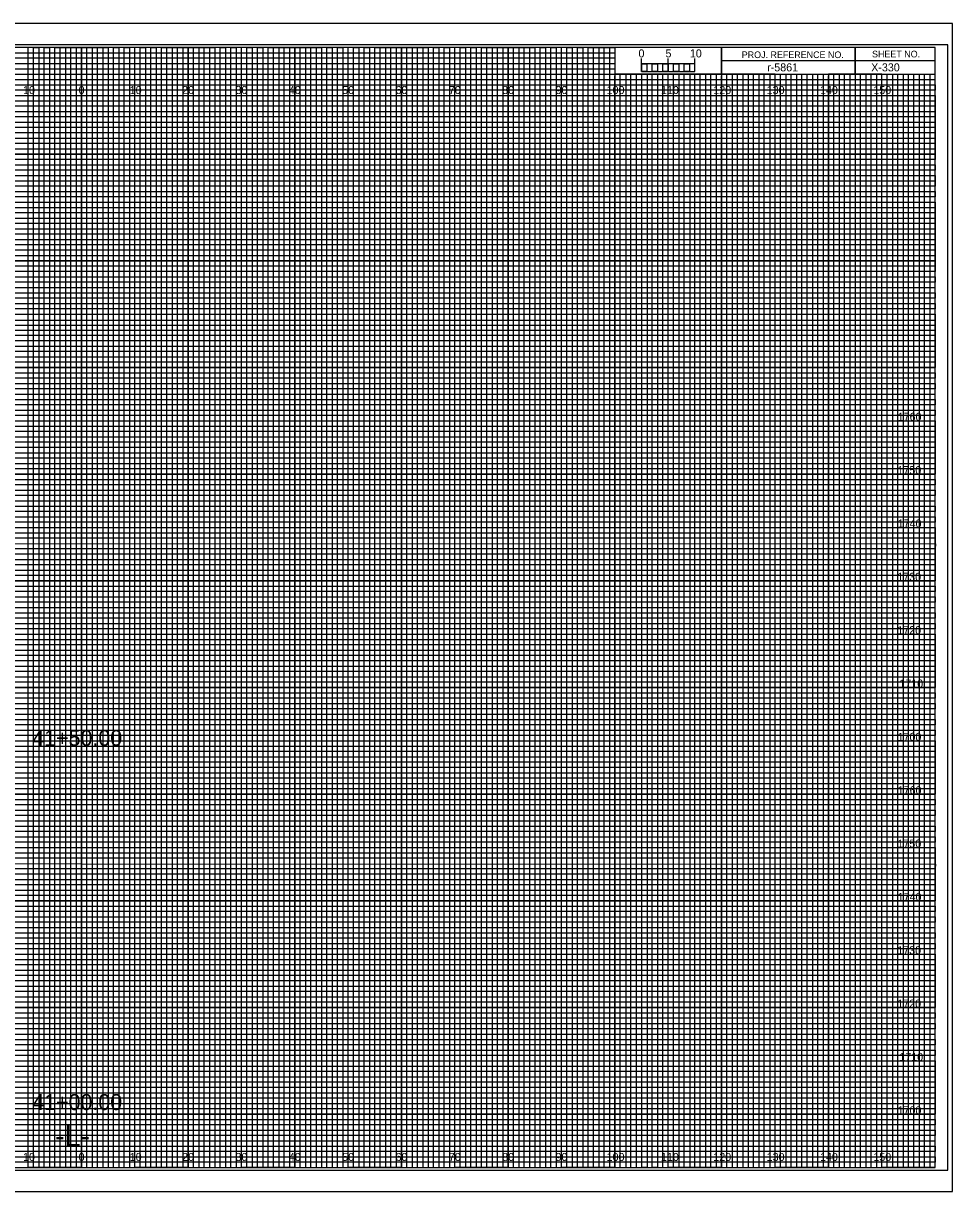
# Model space of a CAD drawing. Extents: x -15 to 323, y -5 to 6170.
# Drawn here: x 149.1 to 323.3, y 5715.5 to 5934.5 of the extents above; entities that cross this region are included whole.
import ezdxf

# ---------------------------------------------------------------- set-up
doc = ezdxf.new("R2010")
doc.units = 0
for name, color, linetype in [('Prop XS Alignment Label', 7, 'Continuous'), ('Prop XS Bar Scale Labels', 7, 'Continuous'), ('Prop XS DDE', 7, 'Continuous'), ('Prop XS DDE Earthwork Shape', 7, 'Continuous'), ('Prop XS DDE Slope Text', 7, 'Continuous'), ('Prop XS DDE Text', 7, 'Continuous'), ('Prop XS Earthwork Shape', 7, 'Continuous'), ('Prop XS Noise Wall', 7, 'Continuous'), ('Prop XS Project Number', 7, 'Continuous'), ('Prop XS Retaining Wall', 7, 'Continuous'), ('Prop XS Station Labels', 7, 'Continuous'), ('Prop XS Temporary Shoring', 7, 'Continuous'), ('Scratch_Level_3', 7, 'Continuous'), ('Scratch_Level_7', 7, 'Continuous'), ('Scratch_Level_8', 7, 'Continuous'), ('Sheet Cross Section Grid Minor 1 CELL', 7, 'Continuous')]:
    doc.layers.add(name, color=color, linetype=linetype)

msp = doc.modelspace()

# ---------------------------------------------------------------- linework, layer by layer
at = {"layer": 'Prop XS Alignment Label'}
for p, q in [((265, 5925.49), (265, 5927.9)), ((265, 5926.9), (265, 5927.9)), ((270, 5925.49), (270, 5927.9)), ((275, 5925.49), (275, 5927.9)), ((275, 5926.9), (275, 5927.9))]:
    msp.add_line(p, q, dxfattribs=at)
for points in [[(275, 5926.9), (265, 5926.9), (265, 5925.49), (275, 5925.49)], [(265, 5926.9), (266, 5926.9), (266, 5925.49), (265, 5925.49)], [(267, 5926.9), (268, 5926.9), (268, 5925.49), (267, 5925.49)], [(269, 5926.9), (270, 5926.9), (270, 5925.49), (269, 5925.49)], [(271, 5926.9), (272, 5926.9), (272, 5925.49), (271, 5925.49)], [(273, 5926.9), (274, 5926.9), (274, 5925.49), (273, 5925.49)]]:
    msp.add_lwpolyline(points, close=True, dxfattribs=at)
at = {"layer": 'Prop XS DDE'}
msp.add_lwpolyline([(-13.4, 5715.5), (323.3, 5715.5), (323.3, 5934.5), (-13.4, 5934.5)], close=True, dxfattribs=at)
at = {"layer": 'Prop XS DDE Slope Text'}
msp.add_lwpolyline([(-10.8, 5719.5), (322.4, 5719.5), (322.4, 5930.5), (-10.8, 5930.5)], close=True, dxfattribs=at)
at = {"layer": 'Prop XS DDE Text'}
for p, q in [((150, 5720), (150, 5930)), ((160, 5720), (160, 5930)), ((170, 5720), (170, 5930)), ((180, 5720), (180, 5930)), ((190, 5720), (190, 5930)), ((200, 5720), (200, 5930)), ((210, 5720), (210, 5930)), ((220, 5720), (220, 5930)), ((230, 5720), (230, 5930)), ((240, 5720), (240, 5930)), ((250, 5720), (250, 5930)), ((260, 5720), (260, 5924.69)), ((270, 5720), (270, 5924.69)), ((280, 5720), (280, 5924.69)), ((290, 5720), (290, 5924.69)), ((300, 5720), (300, 5924.69)), ((310, 5720), (310, 5924.69)), ((0, 5920), (320, 5920)), ((0, 5910), (320, 5910)), ((0, 5900), (320, 5900)), ((0, 5890), (320, 5890)), ((0, 5880), (320, 5880)), ((0, 5870), (320, 5870)), ((0, 5860), (320, 5860)), ((0, 5850), (320, 5850)), ((0, 5840), (320, 5840)), ((0, 5830), (320, 5830)), ((0, 5820), (320, 5820)), ((0, 5810), (320, 5810)), ((0, 5800), (320, 5800)), ((0, 5790), (320, 5790)), ((0, 5780), (320, 5780)), ((0, 5770), (320, 5770)), ((0, 5760), (320, 5760)), ((0, 5750), (320, 5750)), ((0, 5740), (320, 5740)), ((0, 5730), (320, 5730))]:
    msp.add_line(p, q, dxfattribs=at)
at = {"layer": 'Prop XS Earthwork Shape'}
for p, q in [((150, 5930), (140, 5930)), ((150, 5720), (150, 5930)), ((170, 5930), (160, 5930)), ((160, 5930), (160, 5720)), ((170, 5720), (170, 5930)), ((190, 5930), (180, 5930)), ((180, 5930), (180, 5720)), ((190, 5720), (190, 5930)), ((210, 5930), (200, 5930)), ((200, 5930), (200, 5720)), ((210, 5720), (210, 5930)), ((230, 5930), (220, 5930)), ((220, 5930), (220, 5720)), ((230, 5720), (230, 5930)), ((250, 5930), (240, 5930)), ((240, 5930), (240, 5720)), ((250, 5720), (250, 5930)), ((260, 5930), (260, 5720)), ((270, 5720), (270, 5925)), ((290, 5925), (280, 5925)), ((280, 5925), (280, 5720)), ((290, 5720), (290, 5925)), ((310, 5925), (300, 5925)), ((300, 5925), (300, 5720)), ((310, 5720), (310, 5925)), ((160, 5720), (150, 5720)), ((180, 5720), (170, 5720)), ((200, 5720), (190, 5720)), ((220, 5720), (210, 5720)), ((240, 5720), (230, 5720)), ((260, 5720), (250, 5720)), ((280, 5720), (270, 5720)), ((300, 5720), (290, 5720)), ((320, 5720), (310, 5720)), ((320, 5720), (320, 5720))]:
    msp.add_line(p, q, dxfattribs=at)
for points in [[(0, 5920), (320, 5920), (320, 5910), (0, 5910)], [(0, 5900), (320, 5900), (320, 5890), (0, 5890)], [(0, 5880), (320, 5880), (320, 5870), (0, 5870)], [(0, 5860), (320, 5860), (320, 5850), (0, 5850)], [(0, 5840), (320, 5840), (320, 5830), (0, 5830)], [(0, 5820), (320, 5820), (320, 5810), (0, 5810)], [(0, 5800), (320, 5800), (320, 5790), (0, 5790)], [(0, 5780), (320, 5780), (320, 5770), (0, 5770)], [(0, 5760), (320, 5760), (320, 5750), (0, 5750)], [(0, 5740), (320, 5740), (320, 5730), (0, 5730)]]:
    msp.add_lwpolyline(points, dxfattribs=at)
at = {"layer": 'Prop XS Noise Wall'}
for p, q in [((305, 5930), (305, 5925)), ((305, 5925), (305, 5930)), ((280, 5927.5), (280, 5925)), ((320, 5927.49), (280, 5927.49)), ((280, 5925), (320, 5925))]:
    msp.add_line(p, q, dxfattribs=at)
for points in [[(320, 5930), (0, 5930), (0, 5720), (320, 5720)], [(280, 5930), (260, 5930), (260, 5925.03), (280, 5925.03)], [(320, 5930), (280, 5930), (280, 5925), (320, 5925)]]:
    msp.add_lwpolyline(points, close=True, dxfattribs=at)
at = {"layer": 'Prop XS Retaining Wall'}
for p, q in [((267, 5925), (266.01, 5925)), ((266.01, 5925), (266.01, 5720)), ((267, 5720), (267, 5925)), ((269, 5925), (268, 5925)), ((268, 5925), (268, 5720)), ((269, 5720), (269, 5925)), ((266.01, 5720), (265, 5720)), ((268, 5720), (267, 5720))]:
    msp.add_line(p, q, dxfattribs=at)
for points in [[(150, 5720), (151, 5720), (151, 5930), (152, 5930), (152, 5720)], [(152, 5720), (153, 5720), (153, 5930), (154, 5930), (154, 5720)], [(155, 5720), (156, 5720), (156, 5930), (157, 5930), (157, 5720)], [(157, 5720), (158, 5720), (158, 5930), (159, 5930), (159, 5720)], [(160, 5720), (161, 5720), (161, 5930), (162, 5930), (162, 5720)], [(162, 5720), (163, 5720), (163, 5930), (164, 5930), (164, 5720)], [(165, 5720), (166, 5720), (166, 5930), (167, 5930), (167, 5720)], [(167, 5720), (168, 5720), (168, 5930), (169, 5930), (169, 5720)], [(170, 5720), (171, 5720), (171, 5930), (172, 5930), (172, 5720)], [(172, 5720), (173, 5720), (173, 5930), (174, 5930), (174, 5720)], [(175, 5720), (176, 5720), (176, 5930), (177, 5930), (177, 5720)], [(177, 5720), (178, 5720), (178, 5930), (179, 5930), (179, 5720)], [(180, 5720), (181, 5720), (181, 5930), (182, 5930), (182, 5720)], [(182, 5720), (183, 5720), (183, 5930), (184, 5930), (184, 5720)], [(185, 5720), (186, 5720), (186, 5930), (187, 5930), (187, 5720)], [(187, 5720), (188, 5720), (188, 5930), (189, 5930), (189, 5720)], [(190, 5720), (191, 5720), (191, 5930), (192, 5930), (192, 5720)], [(192, 5720), (193, 5720), (193, 5930), (194, 5930), (194, 5720)], [(195, 5720), (196, 5720), (196, 5930), (197, 5930), (197, 5720)], [(197, 5720), (198, 5720), (198, 5930), (199, 5930), (199, 5720)], [(200, 5720), (201, 5720), (201, 5930), (202, 5930), (202, 5720)], [(202, 5720), (203, 5720), (203, 5930), (204, 5930), (204, 5720)], [(205, 5720), (206, 5720), (206, 5930), (207, 5930), (207, 5720)], [(207, 5720), (208, 5720), (208, 5930), (209, 5930), (209, 5720)], [(210, 5720), (211, 5720), (211, 5930), (212, 5930), (212, 5720)], [(212, 5720), (213, 5720), (213, 5930), (214, 5930), (214, 5720)], [(215, 5720), (216, 5720), (216, 5930), (217, 5930), (217, 5720)], [(217, 5720), (218, 5720), (218, 5930), (219, 5930), (219, 5720)], [(220, 5720), (221, 5720), (221, 5930), (222, 5930), (222, 5720)], [(222, 5720), (223, 5720), (223, 5930), (224, 5930), (224, 5720)], [(225, 5720), (226, 5720), (226, 5930), (227, 5930), (227, 5720)], [(227, 5720), (228, 5720), (228, 5930), (229, 5930), (229, 5720)], [(230, 5720), (231, 5720), (231, 5930), (232, 5930), (232, 5720)], [(232, 5720), (233, 5720), (233, 5930), (234, 5930), (234, 5720)], [(235, 5720), (236, 5720), (236, 5930), (237, 5930), (237, 5720)], [(237, 5720), (238, 5720), (238, 5930), (239, 5930), (239, 5720)], [(240, 5720), (241, 5720), (241, 5930), (242, 5930), (242, 5720)], [(242, 5720), (243, 5720), (243, 5930), (244, 5930), (244, 5720)], [(245, 5720), (246, 5720), (246, 5930), (247, 5930), (247, 5720)], [(247, 5720), (248, 5720), (248, 5930), (249, 5930), (249, 5720)], [(250, 5720), (251, 5720), (251, 5930), (252, 5930), (252, 5720)], [(252, 5720), (253, 5720), (253, 5930), (254, 5930), (254, 5720)], [(255, 5720), (256, 5720), (256, 5930), (257, 5930), (257, 5720)], [(257, 5720), (258, 5720), (258, 5930), (259, 5930), (259, 5720)], [(260, 5720), (261, 5720), (261, 5925), (262.02, 5925), (262.02, 5720)], [(262, 5720), (263, 5720), (263, 5925), (263.99, 5925), (263.99, 5720)], [(270, 5720), (270.98, 5720), (270.98, 5925), (272, 5925), (272, 5720)], [(272, 5720), (273, 5720), (273, 5925), (274.05, 5925), (274.05, 5720)], [(275, 5720), (276, 5720), (276, 5925), (277, 5925), (277, 5720)], [(277, 5720), (278, 5720), (278, 5925), (279, 5925), (279, 5720)], [(280, 5720), (281, 5720), (281, 5925), (282, 5925), (282, 5720)], [(282, 5720), (283, 5720), (283, 5925), (284, 5925), (284, 5720)], [(285, 5720), (286, 5720), (286, 5925), (287, 5925), (287, 5720)], [(287, 5720), (288, 5720), (288, 5925), (289, 5925), (289, 5720)], [(290, 5720), (291, 5720), (291, 5925), (292, 5925), (292, 5720)], [(292, 5720), (293, 5720), (293, 5925), (294, 5925), (294, 5720)], [(295, 5720), (296, 5720), (296, 5925), (297, 5925), (297, 5720)], [(297, 5720), (298, 5720), (298, 5925), (299, 5925), (299, 5720)], [(300, 5720), (301, 5720), (301, 5925), (302, 5925), (302, 5720)], [(302, 5720), (303, 5720), (303, 5925), (304, 5925), (304, 5720)], [(305, 5720), (306, 5720), (306, 5925), (307, 5925), (307, 5720)], [(307, 5720), (308, 5720), (308, 5925), (309, 5925), (309, 5720)], [(310, 5720), (311, 5720), (311, 5925), (312, 5925), (312, 5720)], [(312, 5720), (313, 5720), (313, 5925), (314, 5925), (314, 5720)], [(315, 5720), (316, 5720), (316, 5925), (317, 5925), (317, 5720)], [(317, 5720), (318, 5720), (318, 5925), (319, 5925), (319, 5720)]]:
    msp.add_lwpolyline(points, dxfattribs=at)
at = {"layer": 'Prop XS Station Labels'}
for points in [[(145, 5720), (155, 5720), (155, 5930), (165, 5930), (165, 5720), (175, 5720), (175, 5930), (185, 5930), (185, 5720), (195, 5720), (195, 5930), (205, 5930), (205, 5720), (215, 5720), (215, 5930), (225, 5930), (225, 5720), (235, 5720), (235, 5930), (245, 5930), (245, 5720), (255, 5720), (255, 5930), (259.93, 5930), (260, 5930), (260, 5925), (264.99, 5925), (264.99, 5720), (275, 5720), (275, 5925), (285, 5925), (285, 5720), (295, 5720), (295, 5925), (305, 5925), (305, 5720), (315, 5720), (315, 5925)], [(0, 5925), (275, 5925)], [(0, 5905), (320, 5905), (320, 5915), (0, 5915)], [(0, 5885), (320, 5885), (320, 5895), (0, 5895)], [(0, 5865), (320, 5865), (320, 5875), (0, 5875)], [(0, 5845), (320, 5845), (320, 5855), (0, 5855)], [(0, 5825), (320, 5825), (320, 5835), (0, 5835)], [(0, 5805), (320, 5805), (320, 5815), (0, 5815)], [(0, 5785), (320, 5785), (320, 5795), (0, 5795)], [(0, 5765), (320, 5765), (320, 5775), (0, 5775)], [(0, 5745), (320, 5745), (320, 5755), (0, 5755)], [(0, 5725), (320, 5725), (320, 5735), (0, 5735)]]:
    msp.add_lwpolyline(points, dxfattribs=at)
at = {"layer": 'Scratch_Level_7'}
for p, q in [((323.3, 5934.5), (-13.4, 5934.5)), ((-13.4, 5715.5), (323.3, 5715.5))]:
    msp.add_line(p, q, dxfattribs=at)
at = {"layer": 'Sheet Cross Section Grid Minor 1 CELL'}
for p, q in [((0, 5929), (260, 5929)), ((260, 5929), (260, 5927.98)), ((260, 5927.98), (0, 5927.98)), ((0, 5927), (260, 5927)), ((260, 5927), (260, 5925.89)), ((260, 5925.89), (0, 5925.89)), ((0, 5924), (320, 5924))]:
    msp.add_line(p, q, dxfattribs=at)
for points in [[(0, 5923), (270, 5923), (320, 5923), (320, 5922), (0, 5922)], [(0, 5921), (320, 5921), (320, 5919), (0, 5919)], [(0, 5918), (320, 5918), (320, 5917), (0, 5916.98)], [(0, 5916), (320, 5916), (320, 5914), (0, 5914)], [(0, 5913), (320, 5913), (320, 5912), (0, 5912)], [(0, 5911), (320, 5911), (320, 5909), (0, 5909)], [(0, 5908), (320, 5908), (320, 5907), (0, 5907)], [(0, 5906), (320, 5906), (320, 5904), (0, 5904)], [(0, 5903), (320, 5903), (320, 5902), (0, 5902)], [(0, 5901), (320, 5901), (320, 5899), (0, 5899)], [(0, 5898), (320, 5898), (320, 5897), (0, 5897)], [(0, 5896), (320, 5896), (320, 5893.95), (320, 5893), (320, 5892), (0, 5892)], [(0, 5894), (320, 5894), (320, 5893), (0, 5893)], [(0, 5891), (320, 5891), (320, 5889), (0, 5889.03)], [(0, 5889.03), (320, 5889), (320, 5888), (0, 5888)], [(0, 5887), (320, 5887), (320, 5886), (0, 5886)], [(0, 5884), (320, 5884), (320, 5883), (0, 5883)], [(0, 5882), (320, 5882), (320, 5881), (0, 5881)], [(-0.07, 5878.89), (320, 5878.89), (320, 5877.88), (-0.07, 5877.88)], [(0, 5877), (320, 5877), (320, 5876), (0, 5876)], [(0, 5874), (320, 5874), (320, 5873), (0, 5873)], [(0, 5872), (320, 5872), (320, 5871), (0, 5871)], [(0, 5869), (320, 5869), (320, 5868), (0, 5868)], [(0, 5867), (320, 5867), (320, 5866), (0, 5866)], [(0, 5864), (320, 5864), (320, 5863), (0, 5863)], [(0, 5862), (320, 5862), (320, 5861), (0, 5861)], [(0, 5859), (320, 5859), (319.99, 5857.98), (0, 5858)], [(0, 5857), (320, 5857), (320, 5856), (0, 5856)], [(0, 5854), (320, 5854), (320, 5853), (0, 5853)], [(0, 5852), (320, 5852), (320, 5851), (0, 5851)], [(0, 5849), (320, 5849), (320, 5848), (0, 5848)], [(0, 5847), (320, 5847), (320, 5846), (0, 5846)], [(0, 5844), (320, 5844), (320, 5843), (0, 5843)], [(0, 5842), (320, 5842), (320, 5841), (0, 5841)], [(0, 5839), (320, 5839), (320, 5838), (0, 5838)], [(0, 5836.99), (320.07, 5836.91), (320, 5836), (0, 5836)], [(0, 5834), (320, 5834), (320, 5833), (0, 5833)], [(0, 5832), (320, 5832), (320, 5831), (0, 5831)], [(0, 5829), (320, 5829), (320, 5828), (0, 5828)], [(0, 5827), (320, 5827), (320, 5826), (0, 5826)], [(0, 5824), (320, 5824), (320, 5823), (0, 5823)], [(0, 5822), (320, 5822), (320, 5821), (0, 5821)], [(0, 5819), (320, 5819), (320, 5818), (0, 5818)], [(0, 5817), (320, 5817), (320, 5816), (0, 5816)], [(0, 5814), (320, 5814), (320, 5813), (0, 5813)], [(0, 5812), (320, 5812), (320, 5811), (0, 5811)], [(0, 5809), (320, 5809), (320, 5808), (0, 5808)], [(0, 5807), (320, 5807), (320, 5806), (0, 5806)], [(0, 5804), (320, 5804), (320, 5803), (0, 5803)], [(0, 5802), (320, 5802), (320, 5801), (0, 5801)], [(0, 5799), (320, 5799), (319.99, 5797.98), (0, 5798)], [(0, 5797), (320, 5797), (320, 5796), (0, 5796)], [(0, 5794), (320, 5794), (320, 5793), (0, 5793)], [(0, 5792), (320, 5792), (320, 5791), (0, 5791)], [(0, 5789), (320, 5789), (320, 5788), (0, 5788)], [(0, 5787), (320, 5787), (320, 5786), (0, 5786)], [(0, 5784), (320, 5784), (320, 5783), (0, 5783)], [(0, 5782), (320, 5782), (320, 5781), (0, 5781)], [(0, 5779), (320, 5779), (320, 5778), (0, 5778)], [(0, 5776.99), (320.07, 5776.91), (320, 5776), (0, 5776)], [(0, 5774), (320, 5774), (320, 5773), (0, 5773)], [(0, 5772), (320, 5772), (320, 5771), (0, 5771)], [(0, 5769), (320, 5769), (320, 5768), (0, 5768)], [(0, 5767), (320, 5767), (320, 5766), (0, 5766)], [(0, 5764), (320, 5764), (320, 5763), (0, 5763)], [(0, 5762), (320, 5762), (320, 5761), (0, 5761)], [(0, 5759), (320, 5759), (320, 5758), (0, 5758)], [(0, 5757), (320, 5757), (320, 5756), (0, 5756)], [(0, 5754), (320, 5754), (320, 5753), (0, 5753)], [(0, 5752), (320, 5752), (320, 5751), (0, 5751)], [(0, 5749), (320, 5749), (320, 5748), (0, 5748)], [(0, 5747), (320, 5747), (320, 5746), (0, 5746)], [(0, 5744), (320, 5744), (320, 5743), (0, 5743)], [(0, 5742), (320, 5742), (320, 5741), (0, 5741)], [(0, 5739), (320, 5739), (320, 5738), (0, 5738)], [(0, 5737), (320, 5737), (320, 5736), (0, 5736)], [(0, 5734), (320, 5734), (320, 5733), (0, 5733)], [(0, 5732), (320, 5732), (320, 5731), (0, 5731)], [(0, 5729), (320, 5729), (320, 5728), (0, 5728)], [(0, 5727), (320, 5727), (320, 5726), (0, 5726)], [(0, 5724), (320, 5724), (320, 5723), (0, 5723)], [(0, 5722), (320, 5722), (320, 5721), (0, 5721)]]:
    msp.add_lwpolyline(points, dxfattribs=at)

# ---------------------------------------------------------------- texts
at = {"layer": 'Prop XS Alignment Label'}
for s, height, p in [('0', 1.5, (264.41, 5928.12)), ('-L-', 4, (155.06, 5724))]:
    msp.add_text(s, height=height, dxfattribs=at).set_placement(p)
at = {"layer": 'Prop XS Bar Scale Labels'}
for s, p in [('5', (269.47, 5928.12)), ('10', (274.04, 5928.12))]:
    msp.add_text(s, height=1.5, dxfattribs=at).set_placement(p)
at = {"layer": 'Prop XS DDE Earthwork Shape'}
msp.add_text('X-330', height=1.5, dxfattribs=at).set_placement((308.03, 5925.5))
at = {"layer": 'Prop XS Noise Wall'}
for s, p in [('PROJ. REFERENCE NO.', (283.77, 5927.99)), ('SHEET NO.', (308.19, 5928.12))]:
    msp.add_text(s, height=1.25, dxfattribs=at).set_placement(p)
at = {"layer": 'Prop XS Project Number'}
msp.add_text('r-5861', height=1.5, dxfattribs=at).set_placement((288.53, 5925.5))
at = {"layer": 'Prop XS Temporary Shoring'}
for s, p in [('41+50.00', (150.77, 5799.05)), ('41+00.00', (150.77, 5730.79))]:
    msp.add_text(s, height=3, dxfattribs=at).set_placement(p)
at = {"layer": 'Scratch_Level_3'}
for s, p in [('1760', (313, 5860)), ('1750', (312.96, 5850)), ('1740', (313, 5840)), ('1730', (312.92, 5830)), ('1720', (312.93, 5820)), ('1710', (313.31, 5810)), ('1700', (312.98, 5800)), ('1760', (313, 5790)), ('1750', (312.96, 5780)), ('1740', (313, 5770)), ('1730', (312.92, 5760)), ('1720', (312.93, 5750)), ('1710', (313.31, 5740)), ('1700', (312.98, 5730))]:
    msp.add_text(s, height=1.5, dxfattribs=at).set_placement(p)
at = {"layer": 'Scratch_Level_8'}
for s, p in [('10', (149.04, 5921.25)), ('0', (159.45, 5921.25)), ('0', (159.45, 5921.25)), ('10', (169.04, 5921.25)), ('20', (178.86, 5921.25)), ('30', (188.86, 5921.25)), ('40', (198.86, 5921.25)), ('50', (208.86, 5921.25)), ('60', (218.86, 5921.25)), ('70', (228.86, 5921.25)), ('80', (238.86, 5921.25)), ('90', (248.86, 5921.25)), ('100', (258.44, 5921.25)), ('110', (268.62, 5921.25)), ('120', (278.44, 5921.25)), ('130', (288.44, 5921.25)), ('140', (298.44, 5921.25)), ('150', (308.44, 5921.25)), ('10', (149.04, 5721.25)), ('0', (159.45, 5721.25)), ('0', (159.45, 5721.25)), ('10', (169.04, 5721.25)), ('20', (178.86, 5721.25)), ('30', (188.86, 5721.25)), ('40', (198.86, 5721.25)), ('50', (208.86, 5721.25)), ('60', (218.86, 5721.25)), ('70', (228.86, 5721.25)), ('80', (238.86, 5721.25)), ('90', (248.86, 5721.25)), ('100', (258.44, 5721.25)), ('110', (268.62, 5721.25)), ('120', (278.44, 5721.25)), ('130', (288.44, 5721.25)), ('140', (298.44, 5721.25)), ('150', (308.44, 5721.25))]:
    msp.add_text(s, height=1.5, dxfattribs=at).set_placement(p)

doc.saveas('drawing.dxf')
